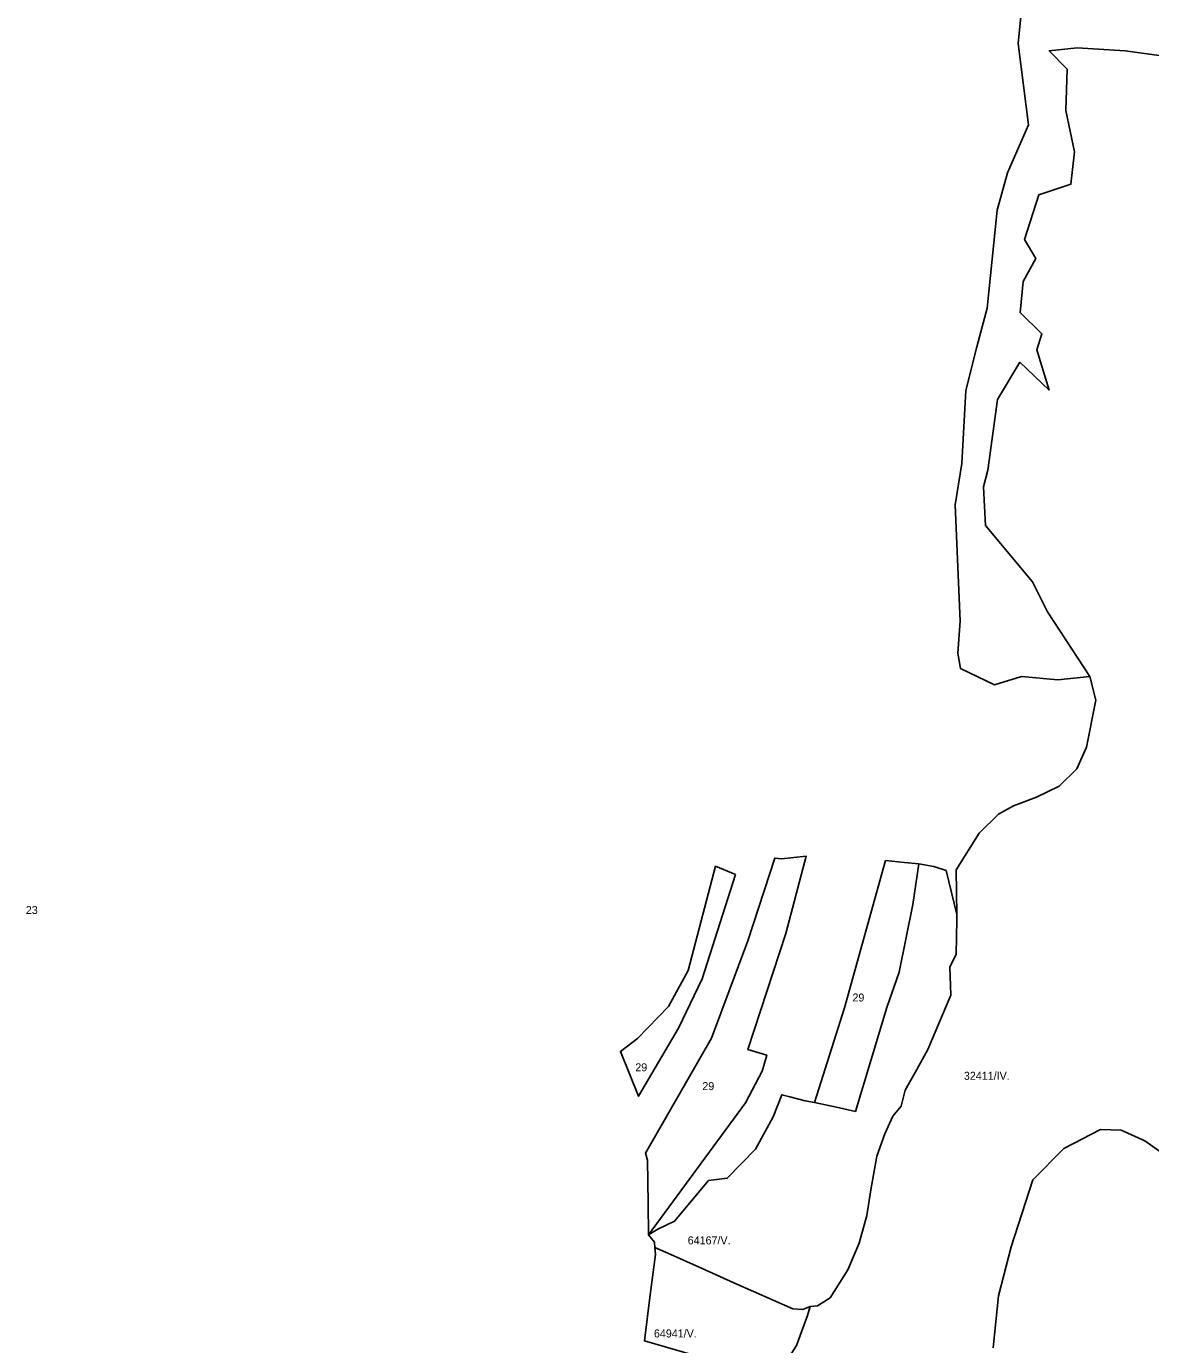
# Model space of a CAD drawing. Extents: x -521621 to -516761, y -1190184 to -1184927.
# Drawn here: x -519242 to -518679, y -1186003 to -1185343 of the extents above; entities that cross this region are included whole.
import ezdxf

# ---------------------------------------------------------------- set-up
doc = ezdxf.new("R2010")
doc.units = 0
doc.layers.add('BPEJ_s', color=7, linetype='Continuous')

msp = doc.modelspace()

# ---------------------------------------------------------------- linework, layer by layer
at = {"layer": 'BPEJ_s'}
for points in [[(-518743.53, -1185331.79), (-518745.5, -1185352.09), (-518740.39, -1185392.71), (-518750.88, -1185416.65), (-518756.08, -1185435.33), (-518761.04, -1185484.42), (-518766.17, -1185503.6), (-518771.72, -1185525.48), (-518773.8, -1185561.94), (-518777.12, -1185582.72), (-518774.57, -1185640.78), (-518775.67, -1185656.87), (-518774.35, -1185664.47), (-518757.39, -1185672.63), (-518743.96, -1185668.55), (-518725.79, -1185670.21), (-518709.72, -1185668.55), (-518706.7, -1185680.32), (-518711.43, -1185703.82), (-518716.27, -1185714.68), (-518725.12, -1185723.42), (-518736.38, -1185728.8), (-518747.96, -1185733.22), (-518755.46, -1185737.41), (-518765.01, -1185746.86), (-518776.62, -1185765.24), (-518776.29, -1185787.53), (-518781.62, -1185765.57), (-518787.8, -1185763.49), (-518795.3, -1185762.23), (-518802.42, -1185761.45), (-518811.91, -1185760.52), (-518832.36, -1185834.11), (-518847.45, -1185881.52), (-518852.05, -1185880.59), (-518859.77, -1185878.66), (-518863.73, -1185877.6), (-518868.17, -1185888.61), (-518876.86, -1185904.75), (-518891.03, -1185919.38), (-518900.39, -1185920.44), (-518917.43, -1185940.77), (-518925.82, -1185944.75), (-518930.4, -1185947.72), (-518882, -1185881.74), (-518873.66, -1185865.82), (-518871.27, -1185857.86), (-518880.81, -1185855.08), (-518861.68, -1185796.96), (-518851.58, -1185758.42), (-518864.01, -1185759.62), (-518867.3, -1185759.32), (-518880.81, -1185800.68), (-518898.97, -1185849.37), (-518931.9, -1185906.83), (-518930.9, -1185910.32), (-518930.65, -1185932.01), (-518930.4, -1185947.72), (-518927.41, -1185951.37), (-518927.24, -1185953.94), (-518926.98, -1185957.49), (-518929.68, -1185977.74), (-518932.52, -1186000.68), (-518902.58, -1186009.28)], [(-518644.75, -1185362.24), (-518692, -1185355.65), (-518716.07, -1185354.21), (-518730, -1185355.65), (-518721.06, -1185364.86), (-518721.74, -1185385.57), (-518717.33, -1185406.12), (-518719.16, -1185422.29), (-518735.21, -1185427.68), (-518742.34, -1185450), (-518736.81, -1185459.52), (-518743.04, -1185470.95), (-518744.59, -1185486.54), (-518733.69, -1185497.1), (-518736.16, -1185505.16), (-518730.09, -1185525.3), (-518744.66, -1185511.41), (-518755.93, -1185529.99), (-518760.7, -1185565.3), (-518762.91, -1185573.65), (-518761.89, -1185593.09), (-518738.33, -1185621.23), (-518730.85, -1185636.21), (-518709.72, -1185668.55), (-518725.79, -1185670.21), (-518743.96, -1185668.55), (-518757.39, -1185672.63), (-518774.35, -1185664.47), (-518775.67, -1185656.87), (-518774.57, -1185640.78), (-518777.12, -1185582.72), (-518773.8, -1185561.94), (-518771.72, -1185525.48), (-518766.17, -1185503.6), (-518761.04, -1185484.42), (-518756.08, -1185435.33), (-518750.88, -1185416.65), (-518740.39, -1185392.71), (-518745.5, -1185352.09), (-518743.53, -1185331.79)], [(-518856.42, -1186002.95), (-518850.9, -1185988.03), (-518849.62, -1185983.57), (-518845.96, -1185983.09), (-518839.59, -1185979.19), (-518830.73, -1185965.18), (-518825.06, -1185951.89), (-518821.33, -1185938.06), (-518819.23, -1185925.15), (-518816.26, -1185908.37), (-518812.25, -1185897.09), (-518808.31, -1185888.32), (-518804, -1185883.34), (-518802.08, -1185875.29), (-518797.12, -1185866.58), (-518790.71, -1185854.92), (-518779.19, -1185827.8), (-518779.78, -1185813.6), (-518776.56, -1185807.5), (-518776.32, -1185790.25), (-518776.31, -1185789.37), (-518776.29, -1185787.53), (-518776.62, -1185765.24), (-518765.01, -1185746.86), (-518755.46, -1185737.41), (-518747.96, -1185733.22), (-518736.38, -1185728.8), (-518725.12, -1185723.42), (-518716.27, -1185714.68), (-518711.43, -1185703.82), (-518706.7, -1185680.32), (-518709.72, -1185668.55), (-518730.85, -1185636.21), (-518738.33, -1185621.23), (-518761.89, -1185593.09), (-518762.91, -1185573.65), (-518760.7, -1185565.3), (-518755.93, -1185529.99), (-518744.66, -1185511.41), (-518730.09, -1185525.3), (-518736.16, -1185505.16), (-518733.69, -1185497.1), (-518744.59, -1185486.54), (-518743.04, -1185470.95), (-518736.81, -1185459.52), (-518742.34, -1185450), (-518735.21, -1185427.68), (-518719.16, -1185422.29), (-518717.33, -1185406.12), (-518721.74, -1185385.57), (-518721.06, -1185364.86), (-518730, -1185355.65), (-518716.07, -1185354.21), (-518692, -1185355.65), (-518644.75, -1185362.24)], [(-518758.01, -1186004.22), (-518755.34, -1185978.17), (-518749.13, -1185953.59), (-518738.18, -1185920.14), (-518722.8, -1185904.45), (-518704.45, -1185894.98), (-518694.1, -1185895.27), (-518682.26, -1185900.6), (-518666.88, -1185911.56), (-518653.56, -1185925.17), (-518656.23, -1185952.11), (-518658.59, -1185978.46), (-518663.33, -1185999.19), (-518663.92, -1186020.8)], [(-518666.88, -1185911.56), (-518682.26, -1185900.6), (-518694.1, -1185895.27), (-518704.45, -1185894.98), (-518722.8, -1185904.45), (-518738.18, -1185920.14), (-518749.13, -1185953.59), (-518755.34, -1185978.17), (-518758.01, -1186004.22)]]:
    msp.add_lwpolyline(points, dxfattribs=at)
for points in [[(-518930.4, -1185947.72), (-518930.65, -1185932.01), (-518930.9, -1185910.32), (-518931.9, -1185906.83), (-518898.97, -1185849.37), (-518880.81, -1185800.68), (-518867.3, -1185759.32), (-518864.01, -1185759.62), (-518851.58, -1185758.42), (-518861.68, -1185796.96), (-518880.81, -1185855.08), (-518871.27, -1185857.86), (-518873.66, -1185865.82), (-518882, -1185881.74)], [(-518930.4, -1185947.72), (-518925.82, -1185944.75), (-518917.43, -1185940.77), (-518900.39, -1185920.44), (-518891.03, -1185919.38), (-518876.86, -1185904.75), (-518868.17, -1185888.61), (-518863.73, -1185877.6), (-518859.77, -1185878.66), (-518852.05, -1185880.59), (-518847.45, -1185881.52), (-518836.44, -1185883.91), (-518826.97, -1185885.92), (-518811.23, -1185833.96), (-518805.08, -1185816.4), (-518798.31, -1185782.5), (-518795.3, -1185762.23), (-518787.8, -1185763.49), (-518781.62, -1185765.57), (-518776.29, -1185787.53), (-518776.31, -1185789.37), (-518776.32, -1185790.25), (-518776.56, -1185807.5), (-518779.78, -1185813.6), (-518779.19, -1185827.8), (-518790.71, -1185854.92), (-518797.12, -1185866.58), (-518802.08, -1185875.29), (-518804, -1185883.34), (-518808.31, -1185888.32), (-518812.25, -1185897.09), (-518816.26, -1185908.37), (-518819.23, -1185925.15), (-518821.33, -1185938.06), (-518825.06, -1185951.89), (-518830.73, -1185965.18), (-518839.59, -1185979.19), (-518845.96, -1185983.09), (-518849.62, -1185983.57), (-518853.23, -1185985.04), (-518858.33, -1185984.63), (-518887.75, -1185971.74), (-518903.58, -1185964.54), (-518919.2, -1185957.47), (-518927.24, -1185953.94), (-518927.41, -1185951.37)], [(-518847.45, -1185881.52), (-518832.36, -1185834.11), (-518811.91, -1185760.52), (-518802.42, -1185761.45), (-518795.3, -1185762.23), (-518798.31, -1185782.5), (-518805.08, -1185816.4), (-518811.23, -1185833.96), (-518826.97, -1185885.92), (-518836.44, -1185883.91)], [(-518886.92, -1185767.56), (-518896.95, -1185763.37), (-518910.61, -1185815.42), (-518920.49, -1185833.58), (-518936.01, -1185849.53), (-518944.48, -1185855.98), (-518935.38, -1185878.4), (-518915.4, -1185844.37), (-518903.53, -1185819.65)], [(-518886.92, -1185767.56), (-518896.95, -1185763.37), (-518910.61, -1185815.42), (-518920.49, -1185833.58), (-518936.01, -1185849.53), (-518944.48, -1185855.98), (-518935.38, -1185878.4), (-518915.4, -1185844.37), (-518903.53, -1185819.65)], [(-518927.24, -1185953.94), (-518919.2, -1185957.47), (-518903.58, -1185964.54), (-518887.75, -1185971.74), (-518858.33, -1185984.63), (-518853.23, -1185985.04), (-518849.62, -1185983.57), (-518850.9, -1185988.03), (-518856.42, -1186002.95), (-518861.03, -1186010.39), (-518869.09, -1186015.13), (-518894.47, -1186011.75), (-518902.58, -1186009.28), (-518932.52, -1186000.68), (-518929.68, -1185977.74), (-518926.98, -1185957.49)]]:
    msp.add_lwpolyline(points, close=True, dxfattribs=at)

# ---------------------------------------------------------------- texts
for s, p in [('23', (-519241.86, -1185787.27)), ('29', (-518828.44, -1185831)), ('29', (-518937.04, -1185865.91)), ('32411/IV.', (-518772.7, -1185870.15)), ('29', (-518903.51, -1185875.3)), ('64167/V.', (-518910.83, -1185952.43)), ('64941/V.', (-518927.72, -1185998.97))]:
    msp.add_text(s, height=4, dxfattribs=at).set_placement(p)

doc.saveas('drawing.dxf')
